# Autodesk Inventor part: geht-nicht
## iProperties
Created: 2005-06
Part Number: geht-nicht
Document SubType Name: Modeling
Designer: schlagmann
Manufacturer: Standard
Standards Organization: Custom
Description: Berechnung Füllung Kokille
ZNr: 20-KOK-130-1610
AIMD_DESCRIPTION: 596x1070
AIMD_ORIGIN: ENG-001080
Author: schlagmann
Title: Berechnung Füllung Kokille
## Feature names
1. Erhebung3
2. Trennen1
